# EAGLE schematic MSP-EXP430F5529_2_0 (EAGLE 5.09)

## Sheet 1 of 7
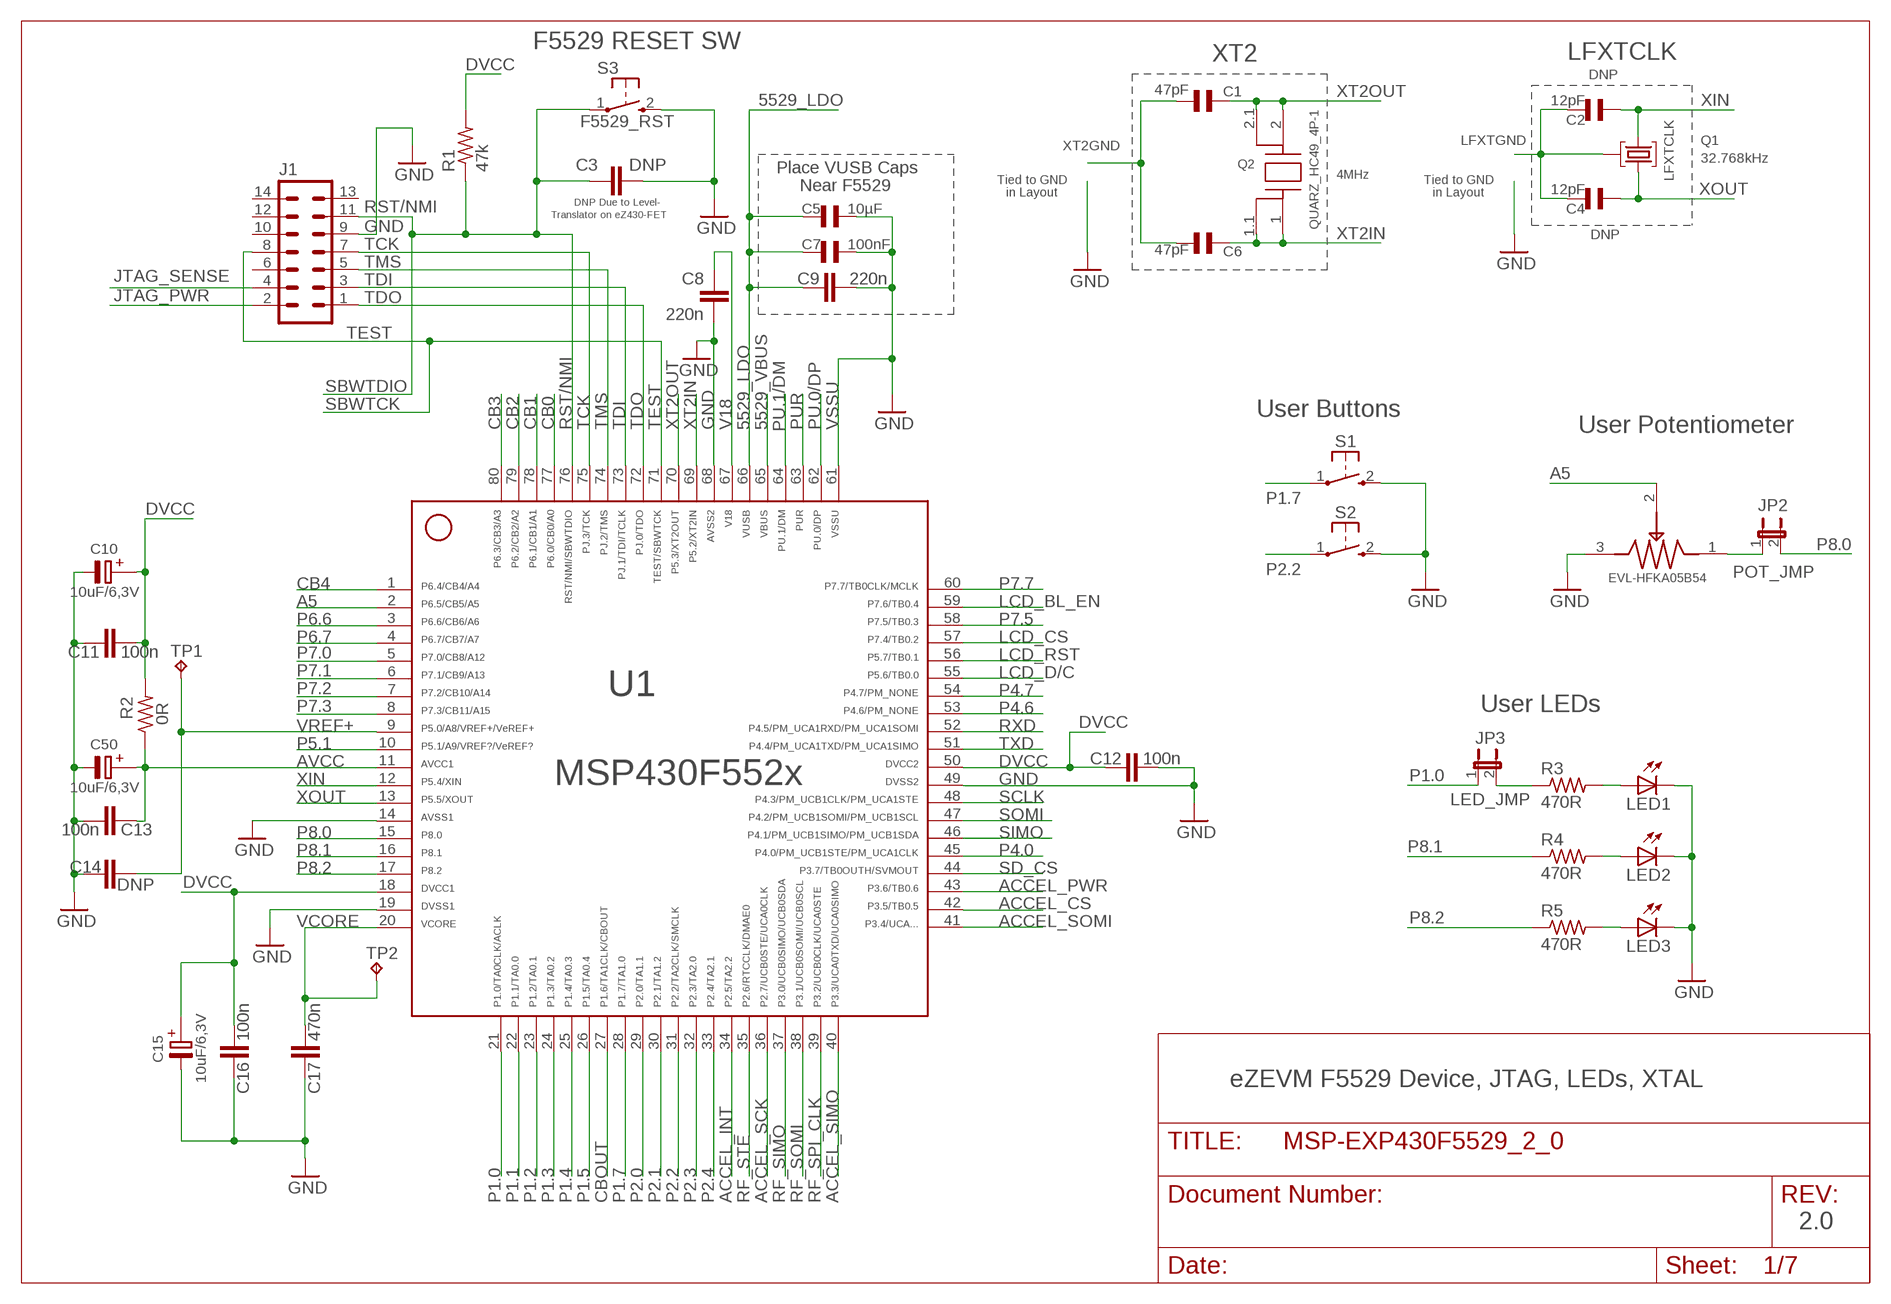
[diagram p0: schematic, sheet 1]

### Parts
C1  47pF  CSMD0805  [CSMD0805]
C2  12pF  CSMD0805  [CSMD0805]
C3  DNP  C-EUC0603  [C0603]
C4  12pF  CSMD0805  [CSMD0805]
C5  10µF  CSMD0805  [CSMD0805]
C6  47pF  CSMD0805  [CSMD0805]
C7  100nF  CSMD0805  [CSMD0805]
C8  220n  C-EUC0603  [C0603]
C9  220n  C-EUC0603  [C0603]
C10  10uF/6,3V  ELKO_1210  [1210ELKO]
C11  100n  C-EUC0603  [C0603]
C12  100n  C-EUC0805  [C0805]
C13  100n  C-EUC0805  [C0805]
C14  DNP  C-EUC0603  [C0603]
C15  10uF/6,3V  ELKO_1210  [1210ELKO]
C16  100n  C-EUC0805  [C0805]
C17  470n  C-EUC0805  [C0805]
C50  10uF/6,3V  ELKO_1210  [1210ELKO]
J1  ML14  [ML14]
JP2  POT_JMP  JP1E\SMALL_PIN  [JP1S]
JP3  LED_JMP  JP1E\SMALL_PIN  [JP1S]
LED1  LEDCHIPLED_0603  [CHIPLED_0603]
LED2  LEDCHIPLED_0603  [CHIPLED_0603]
LED3  LEDCHIPLED_0603  [CHIPLED_0603]
POT1  EVL-HFKA05B54  EVL-HFAA05B54  [EVL-HFAA05B54]
Q1  32.768kHz  F20XX_PIR_DEMO_&_EVAL_CM200T  [F20XX_PIR_DEMO_&_EVAL_CMJ206T]
Q2  QUARZ_HC49_4P-1  [QUARZ_HC49_4P]
R1  47k  R-US_R0603  [R0603]
R2  0R  R-US_R0603  [R0603]
R3  470R  R-US_R0603  [R0603]
R4  470R  R-US_R0603  [R0603]
R5  470R  R-US_R0603  [R0603]
S1  PB  [PBTH]
S2  PB  [PBTH]
S3  F5529_RST  PB  [PBTH]
TP1  TP  [TP]
TP2  TP  [TP]
U1  MSP430F5529IPNR  F552X---PN80  [PN80]

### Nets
5529_LDO [Power]: C5.1 C7.1 C9.1 U1.66 ; also sheet 3,4
5529_VBUS [Power]: U1.65 ; also sheet 3,4
A5: POT1.2(X2) U1.2
ACCEL_CS: U1.42 ; also sheet 2
ACCEL_INT: U1.34 ; also sheet 2
ACCEL_PWR: U1.43 ; also sheet 2
ACCEL_SCK: U1.36 ; also sheet 2
ACCEL_SIMO: U1.40 ; also sheet 2
ACCEL_SOMI: U1.41 ; also sheet 2
AVCC: C13.1 C50.+ R2.1 U1.11
CB0: U1.77 ; also sheet 2
CB1: U1.78 ; also sheet 2
CB2: U1.79 ; also sheet 2
CB3: U1.80 ; also sheet 2
CB4: U1.1 ; also sheet 2
CBOUT: U1.27 ; also sheet 2
DVCC [Power]: C10.+ C11.2 C12.1 C15.+ C16.2 R1.2 R2.2 U1.18 U1.50 ; also sheet 3,5
GND [Ground]: C3.1 C5.2 C7.2 C8.2 C9.2 C10.- C11.1 C12.2 C13.2 C14.1 C15.- C16.1 C17.1 C50.- J1.9 LED1.C LED2.C LED3.C POT1.3(X3) S1.2(S) S2.2(S) S3.2(S) U1.14 U1.19 U1.49 U1.61 U1.68 ; also sheet 2,3,4,5,6
JTAG_PWR [Power]: J1.2 ; also sheet 3
JTAG_SENSE: J1.4 ; also sheet 3
LCD_BL_EN: U1.59 ; also sheet 3
LCD_CS: U1.57 ; also sheet 3
LCD_D/C: U1.55 ; also sheet 3
LCD_RST: U1.56 ; also sheet 3
LFXTGND: C2.2 C4.2 Q1.P3(GND)
N$21: LED3.A R5.2
N$32: LED1.A R3.2
N$35: LED2.A R4.2
N$36: JP3.2 R3.1
N$43: JP2.1 POT1.1(X1)
P1.0: JP3.1 U1.21 ; also sheet 4
P1.1: U1.22 ; also sheet 2
P1.2: U1.23 ; also sheet 2
P1.3: U1.24 ; also sheet 2
P1.4: U1.25 ; also sheet 2
P1.5: U1.26 ; also sheet 2
P1.7: S1.1(P) U1.28
P2.0: U1.29 ; also sheet 4
P2.1: U1.30 ; also sheet 4
P2.2: S2.1(P) U1.31
P2.3: U1.32 ; also sheet 4
P2.4: U1.33 ; also sheet 4
P4.0: U1.45 ; also sheet 2,4
P4.6: U1.53 ; also sheet 2,4
P4.7: U1.54 ; also sheet 2,4
P5.1: U1.10 ; also sheet 2
P6.6: U1.3 ; also sheet 2,4
P6.7: U1.4 ; also sheet 2
P7.0: U1.5 ; also sheet 2
P7.1: U1.6 ; also sheet 2
P7.2: U1.7 ; also sheet 2
P7.3: U1.8 ; also sheet 2
P7.5: U1.58 ; also sheet 4
P7.7: U1.60 ; also sheet 2
P8.0: JP2.2 U1.15 ; also sheet 2
P8.1: R4.1 U1.16 ; also sheet 2
P8.2: R5.1 U1.17 ; also sheet 2
PU.0/DP: U1.62 ; also sheet 4
PU.1/DM: U1.64 ; also sheet 4
PUR: U1.63 ; also sheet 4
RF_SIMO: U1.37 ; also sheet 4
RF_SOMI: U1.38 ; also sheet 4
RF_SPI_CLK: U1.39 ; also sheet 4
RF_STE: U1.35 ; also sheet 4
RST/NMI: C3.2 J1.11 R1.1 S3.1(P) U1.76 ; also sheet 5
RXD: U1.52 ; also sheet 2,4,5
SCLK: U1.48 ; also sheet 2,3
SD_CS: U1.44 ; also sheet 2
SIMO: U1.46 ; also sheet 2,3
SOMI: U1.47 ; also sheet 2
TCK: J1.7 U1.75
TDI: J1.3 U1.73
TDO: J1.1 U1.72
TEST: J1.8 U1.71 ; also sheet 5
TMS: J1.5 U1.74
TXD: U1.51 ; also sheet 2,4,5
V18: C8.1 U1.67
VCORE: C17.2 TP2.1(TP) U1.20
VREF+: C14.2 TP1.1(TP) U1.9
XIN: C2.1 Q1.P2 U1.12
XOUT: C4.1 Q1.P1 U1.13
XT2GND [Ground]: C1.2 C6.2
XT2IN: C6.1 Q2.1 Q2.1.1 U1.69
XT2OUT: C1.1 Q2.2 Q2.2.1 U1.70
Unconnected: J1.6 J1.10 J1.12 J1.13 J1.14

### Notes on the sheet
- F5529 RESET SW
- XT2 | LFXTCLK
- DNP
- Place VUSB Caps | 4MHz
- Tied to GND | Tied to GND | LFXTCLK
- Near F5529
- in Layout | in Layout
- DNP Due to Level-
- Translator on eZ430-FET
- DNP
- SBWTDIO
- SBWTCK
- User Buttons
- VSSU | User Potentiometer
- EVL-HFKA05B54
- User LEDs
- eZEVM F5529 Device, JTAG, LEDs, XTAL
- 2.0

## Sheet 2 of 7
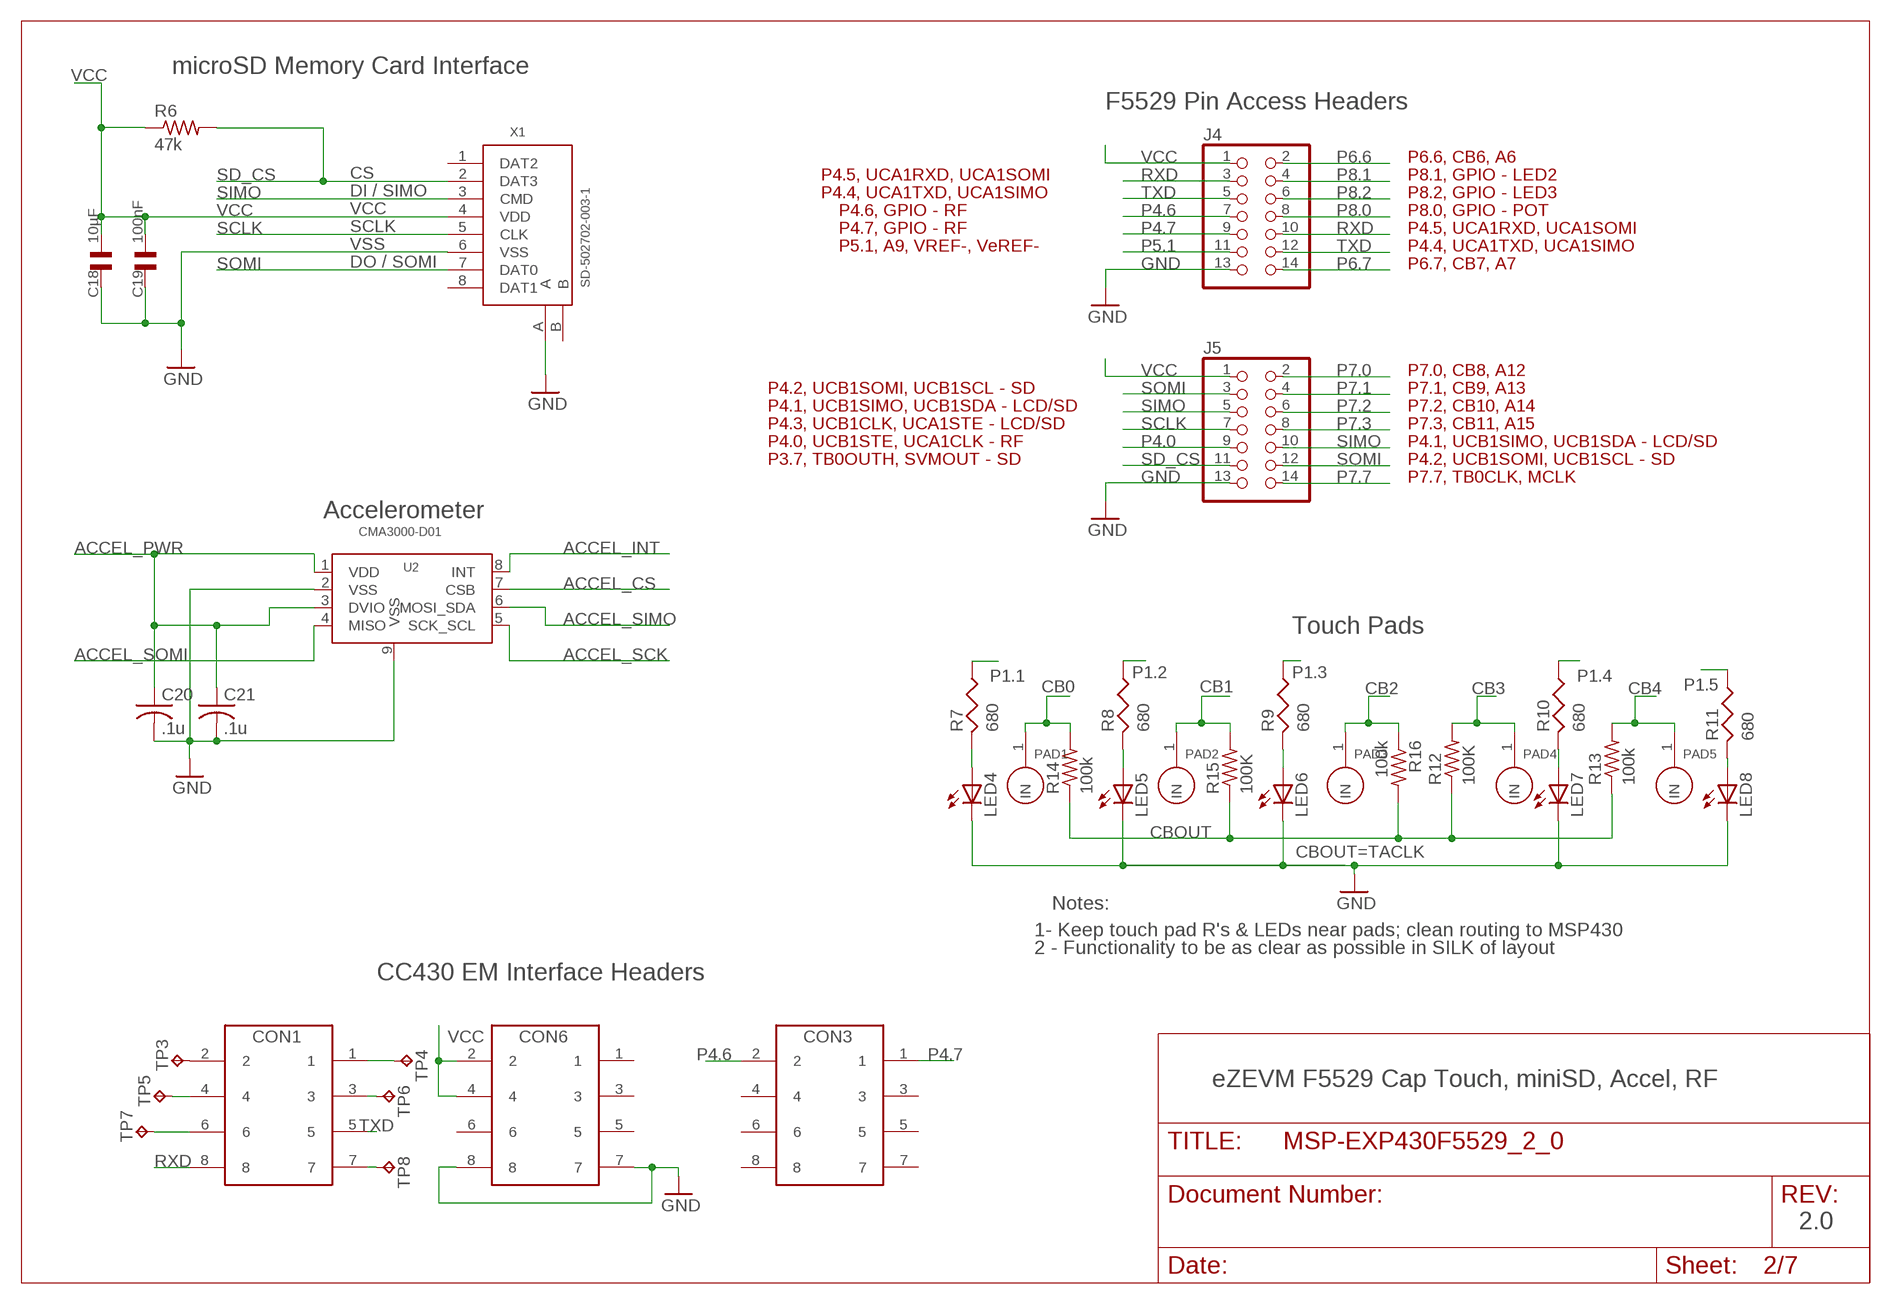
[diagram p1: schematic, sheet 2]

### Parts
C18  10µF  CSMD0805  [CSMD0805]
C19  100nF  CSMD0805  [CSMD0805]
C20  .1u  C-USC0603  [C0603]
C21  .1u  C-USC0603  [C0603]
CON1  8PIN_SM_MA_HEADER  [8PIN_SM_MA_HEADER]
CON2  8PIN_SM_MA_HEADER  [8PIN_SM_MA_HEADER]
CON3  8PIN_SM_MA_HEADER  [8PIN_SM_MA_HEADER]
J4  PINHD-2X7  [2X07]
J5  PINHD-2X7  [2X07]
LED4  LEDTOPLED-SANTANA  [MINI-TOPLED-SANTANA]
LED5  LEDTOPLED-SANTANA  [MINI-TOPLED-SANTANA]
LED6  LEDTOPLED-SANTANA  [MINI-TOPLED-SANTANA]
LED7  LEDTOPLED-SANTANA  [MINI-TOPLED-SANTANA]
LED8  LEDTOPLED-SANTANA  [MINI-TOPLED-SANTANA]
PAD1  PROJECT7264_CC430_PAD  [CC430_PAD_NS]
PAD2  PROJECT7264_CC430_PAD  [CC430_PAD_NS]
PAD3  PROJECT7264_CC430_PAD  [CC430_PAD_NS]
PAD4  PROJECT7264_CC430_PAD  [CC430_PAD_NS]
PAD5  PROJECT7264_CC430_PAD  [CC430_PAD_NS]
R6  47k  R-US_R0603  [R0603]
R7  680  RES0805  [R0805]
R8  680  RES0805  [R0805]
R9  680  RES0805  [R0805]
R10  680  RES0805  [R0805]
R11  680  RES0805  [R0805]
R12  100K  R-US_R0603  [R0603]
R13  100k  R-US_R0603  [R0603]
R14  100k  R-US_R0603  [R0603]
R15  100K  R-US_R0603  [R0603]
R16  100k  R-US_R0603  [R0603]
TP3  TP  [TP]
TP4  TP  [TP]
TP5  TP  [TP]
TP6  TP  [TP]
TP7  TP  [TP]
TP8  TP  [TP]
U2  CMA3000-D01  CMA3000-D01-1  [CMA3000-D01]
X1  SD-502702-003-1  [SD-502702-003]

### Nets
ACCEL_CS: U2.7(CSB) ; also sheet 1
ACCEL_INT: U2.8(INT) ; also sheet 1
ACCEL_PWR: C20.1 C21.1 U2.1(VDD) U2.3(DVIO) ; also sheet 1
ACCEL_SCK: U2.5(SCK_SCL) ; also sheet 1
ACCEL_SIMO: U2.6(MOSI_SDA) ; also sheet 1
ACCEL_SOMI: U2.4(MISO) ; also sheet 1
CB0: PAD1.1(IN) R14.2 ; also sheet 1
CB1: PAD2.1(IN) R15.2 ; also sheet 1
CB2: PAD3.1(IN) R16.1 ; also sheet 1
CB3: PAD4.1(IN) R12.2 ; also sheet 1
CB4: PAD5.1(IN) R13.2 ; also sheet 1
CBOUT: R12.1 R13.1 R14.1 R15.1 R16.2 ; also sheet 1
GND [Ground]: C18.1 C19.1 C20.2 C21.2 CON2.7 CON2.8 J4.13 J5.13 LED4.C LED5.C LED6.C LED7.C LED8.C U2.2(VSS) U2.9(VSS) X1.6(VSS) X1.A ; also sheet 1,3,4,5,6
N$7: LED7.A R10.2
N$8: LED5.A R8.2
N$10: LED6.A R9.2
N$11: LED4.A R7.2
N$12: CON1.6 TP7.1(TP)
N$13: LED8.A R11.2
N$20: CON1.4 TP5.1(TP)
N$27: CON1.2 TP3.1(TP)
N$28: CON1.1 TP4.1(TP)
N$29: CON1.3 TP6.1(TP)
N$38: CON1.7 TP8.1(TP)
P1.1: R7.1 ; also sheet 1
P1.2: R8.1 ; also sheet 1
P1.3: R9.1 ; also sheet 1
P1.4: R10.1 ; also sheet 1
P1.5: R11.1 ; also sheet 1
P4.0: J5.9 ; also sheet 1,4
P4.6: CON3.2 J4.7 ; also sheet 1,4
P4.7: CON3.1 J4.9 ; also sheet 1,4
P5.1: J4.11 ; also sheet 1
P6.6: J4.2 ; also sheet 1,4
P6.7: J4.14 ; also sheet 1
P7.0: J5.2 ; also sheet 1
P7.1: J5.4 ; also sheet 1
P7.2: J5.6 ; also sheet 1
P7.3: J5.8 ; also sheet 1
P7.7: J5.14 ; also sheet 1
P8.0: J4.8 ; also sheet 1
P8.1: J4.4 ; also sheet 1
P8.2: J4.6 ; also sheet 1
RXD: CON1.8 J4.3 J4.10 ; also sheet 1,4,5
SCLK: J5.7 X1.5(CLK) ; also sheet 1,3
SD_CS: J5.11 R6.2 X1.2(DAT3) ; also sheet 1
SIMO: J5.5 J5.10 X1.3(CMD) ; also sheet 1,3
SOMI: J5.3 J5.12 X1.7(DAT0) ; also sheet 1
TXD: CON1.5 J4.5 J4.12 ; also sheet 1,4,5
VCC [Power]: C18.2 C19.2 CON2.2 CON2.4 J4.1 J5.1 R6.1 X1.4(VDD) ; also sheet 3,4
Unconnected: CON2.1 CON2.3 CON2.5 CON2.6 CON3.3 CON3.4 CON3.5 CON3.6 CON3.7 CON3.8 X1.1(DAT2) X1.8(DAT1) X1.B

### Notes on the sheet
- microSD Memory Card Interface
- F5529 Pin Access Headers
- P6.6, CB6, A6
- CS | P4.5, UCA1RXD, UCA1SOMI | P8.1, GPIO - LED2
- DI / SIMO | P4.4, UCA1TXD, UCA1SIMO | P8.2, GPIO - LED3
- VCC | P4.6, GPIO - RF | P8.0, GPIO - POT
- SCLK | P4.7, GPIO - RF | P4.5, UCA1RXD, UCA1SOMI
- VSS | P5.1, A9, VREF-, VeREF- | P4.4, UCA1TXD, UCA1SIMO
- DO / SOMI | P6.7, CB7, A7
- P7.0, CB8, A12
- P4.2, UCB1SOMI, UCB1SCL - SD | P7.1, CB9, A13
- P4.1, UCB1SIMO, UCB1SDA - LCD/SD | P7.2, CB10, A14
- P4.3, UCB1CLK, UCA1STE - LCD/SD | P7.3, CB11, A15
- P4.0, UCB1STE, UCA1CLK - RF | P4.1, UCB1SIMO, UCB1SDA - LCD/SD
- P3.7, TB0OUTH, SVMOUT - SD | P4.2, UCB1SOMI, UCB1SCL - SD
- P7.7, TB0CLK, MCLK
- Accelerometer
- Touch Pads
- CBOUT=TACLK
- Notes:
- 1- Keep touch pad R's & LEDs near pads; clean routing to MSP430
- 2 - Functionality to be as clear as possible in SILK of layout
- CC430 EM Interface Headers
- CON1 | CON6 | CON3
- eZEVM F5529 Cap Touch, miniSD, Accel, RF
- 2.0

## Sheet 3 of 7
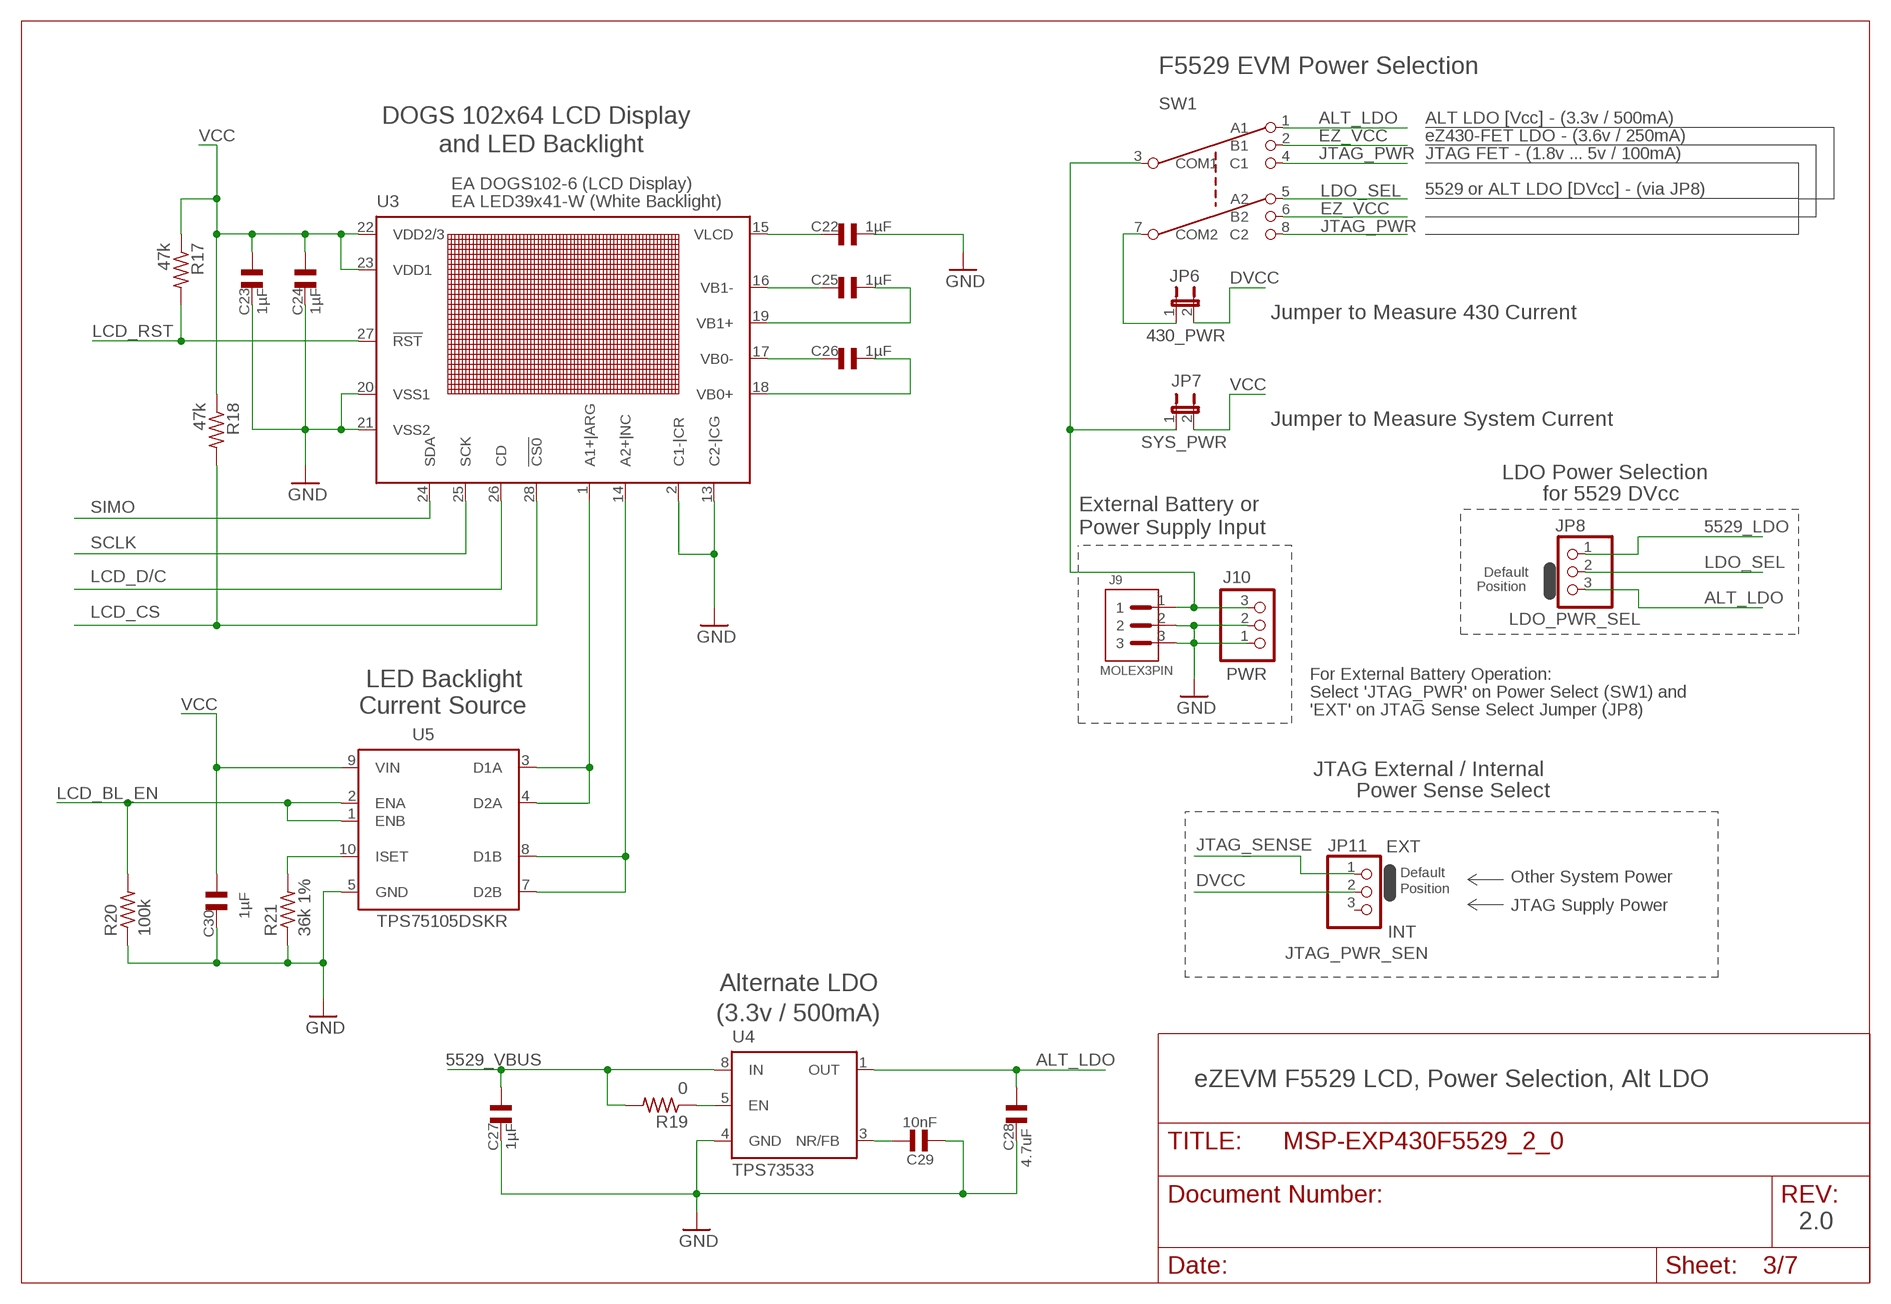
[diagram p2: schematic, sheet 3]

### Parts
C22  1µF  CSMD0805  [CSMD0805]
C23  1µF  CSMD0805  [CSMD0805]
C24  1µF  CSMD0805  [CSMD0805]
C25  1µF  CSMD0805  [CSMD0805]
C26  1µF  CSMD0805  [CSMD0805]
C27  1µF  CSMD0805  [CSMD0805]
C28  4.7uF  CSMD0805  [CSMD0805]
C29  10nF  CSMD0805  [CSMD0805]
C30  1µF  CSMD0805  [CSMD0805]
J9  MOLEX3PIN  [MOLEX-3P-HEADER]
J10  PWR  PINHD-1X3  [1X03]
JP6  430_PWR  JP1E  [JP1]
JP7  SYS_PWR  JP1E  [JP1]
JP8  LDO_PWR_SEL  PINHD-1X3/SMALL_PIN  [1X03S]
JP11  JTAG_PWR_SEN  PINHD-1X3/SMALL_PIN  [1X03S]
R17  47k  R-US_R0603  [R0603]
R18  47k  R-US_R0603  [R0603]
R19  0  R-US_R0603  [R0603]
R20  100k  R-US_R0603  [R0603]
R21  36k 1%  R-US_R0603  [R0603]
SW1  3PDT  [3PDT]
U3  EA DOGS102-6 (LCD Display)  EADOGS102-6  [EADOGS102-6]
U4  TPS73533  TPS735  [DRB_S-PVSON-N8]
U5  TPS75105DSKR  TPS7510X  [DSK_S-PDSO-N10]

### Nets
5529_LDO [Power]: JP8.1 ; also sheet 1,4
5529_VBUS [Power]: C27.2 R19.2 U4.8(IN) ; also sheet 1,4
ALT_LDO [Power]: C28.2 JP8.3 SW1.1(A1) U4.1(OUT)
D1A: U3.1(A1+|ARG) U5.3(D1A) U5.4(D2A)
D1B: U3.14(A2+|NC) U5.7(D2B) U5.8(D1B)
DVCC [Power]: JP6.2 JP11.2 ; also sheet 1,5
DVCC_SW [Power]: JP6.1 SW1.7(COM2)
EZ_VCC [Power]: SW1.2(B1) SW1.6(B2) ; also sheet 5,6
GND [Ground]: C22.2 C23.1 C24.1 C27.1 C28.1 C29.1 C30.1 J9.2 J9.3 J10.1 J10.2 R20.1 R21.1 U3.2(C1-|CR) U3.13(C2-|CG) U3.20(VSS1) U3.21(VSS2) U4.4(GND) U5.5(GND) ; also sheet 1,2,4,5,6
ISET: R21.2 U5.10(ISET)
JTAG_PWR [Power]: SW1.4(C1) SW1.8(C2) ; also sheet 1
JTAG_SENSE: JP11.1 ; also sheet 1
LCD_BL_EN: R20.2 U5.1(ENB) U5.2(ENA) ; also sheet 1
LCD_CS: R18.2 U3.28(!CS0) ; also sheet 1
LCD_D/C: U3.26(CD) ; also sheet 1
LCD_RST: R17.2 U3.27(!RST) ; also sheet 1
LDO_SEL [Power]: JP8.2 SW1.5(A2)
N$14: R19.1 U4.5(EN)
N$41: C25.1 U3.16(VB1-)
N$44: C25.2 U3.19(VB1+)
N$45: C26.1 U3.17(VB0-)
N$46: C26.2 U3.18(VB0+)
N$50: C29.2 U4.3(NR/FB)
SCLK: U3.25(SCK) ; also sheet 1,2
SIMO: U3.24(SDA) ; also sheet 1,2
VCC [Power]: C23.2 C24.2 C30.2 JP7.2 R17.1 R18.1 U3.22(VDD2/3) U3.23(VDD1) U5.9(VIN) ; also sheet 2,4
VCC_SW [Power]: J9.1 J10.3 JP7.1 SW1.3(COM1)
VLCD: C22.1 U3.15(VLCD)
Unconnected: JP11.3

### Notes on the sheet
- F5529 EVM Power Selection
- DOGS 102x64 LCD Display | ALT LDO [Vcc] - (3.3v / 500mA)
- eZ430-FET LDO - (3.6v / 250mA)
- and LED Backlight
- JTAG FET - (1.8v ... 5v / 100mA)
- 5529 or ALT LDO [DVcc] - (via JP8)
- EA LED39x41-W (White Backlight)
- Jumper to Measure 430 Current
- Jumper to Measure System Current
- LDO Power Selection
- for 5529 DVcc
- External Battery or
- Power Supply Input
- Default
- Position
- For External Battery Operation:
- LED Backlight
- Select 'JTAG_PWR' on Power Select (SW1) and
- Current Source | 'EXT' on JTAG Sense Select Jumper (JP8)
- JTAG External / Internal
- Power Sense Select
- EXT
- Default
- Other System Power
- Position
- JTAG Supply Power
- INT
- Alternate LDO
- (3.3v / 500mA)
- eZEVM F5529 LCD, Power Selection, Alt LDO
- 2.0

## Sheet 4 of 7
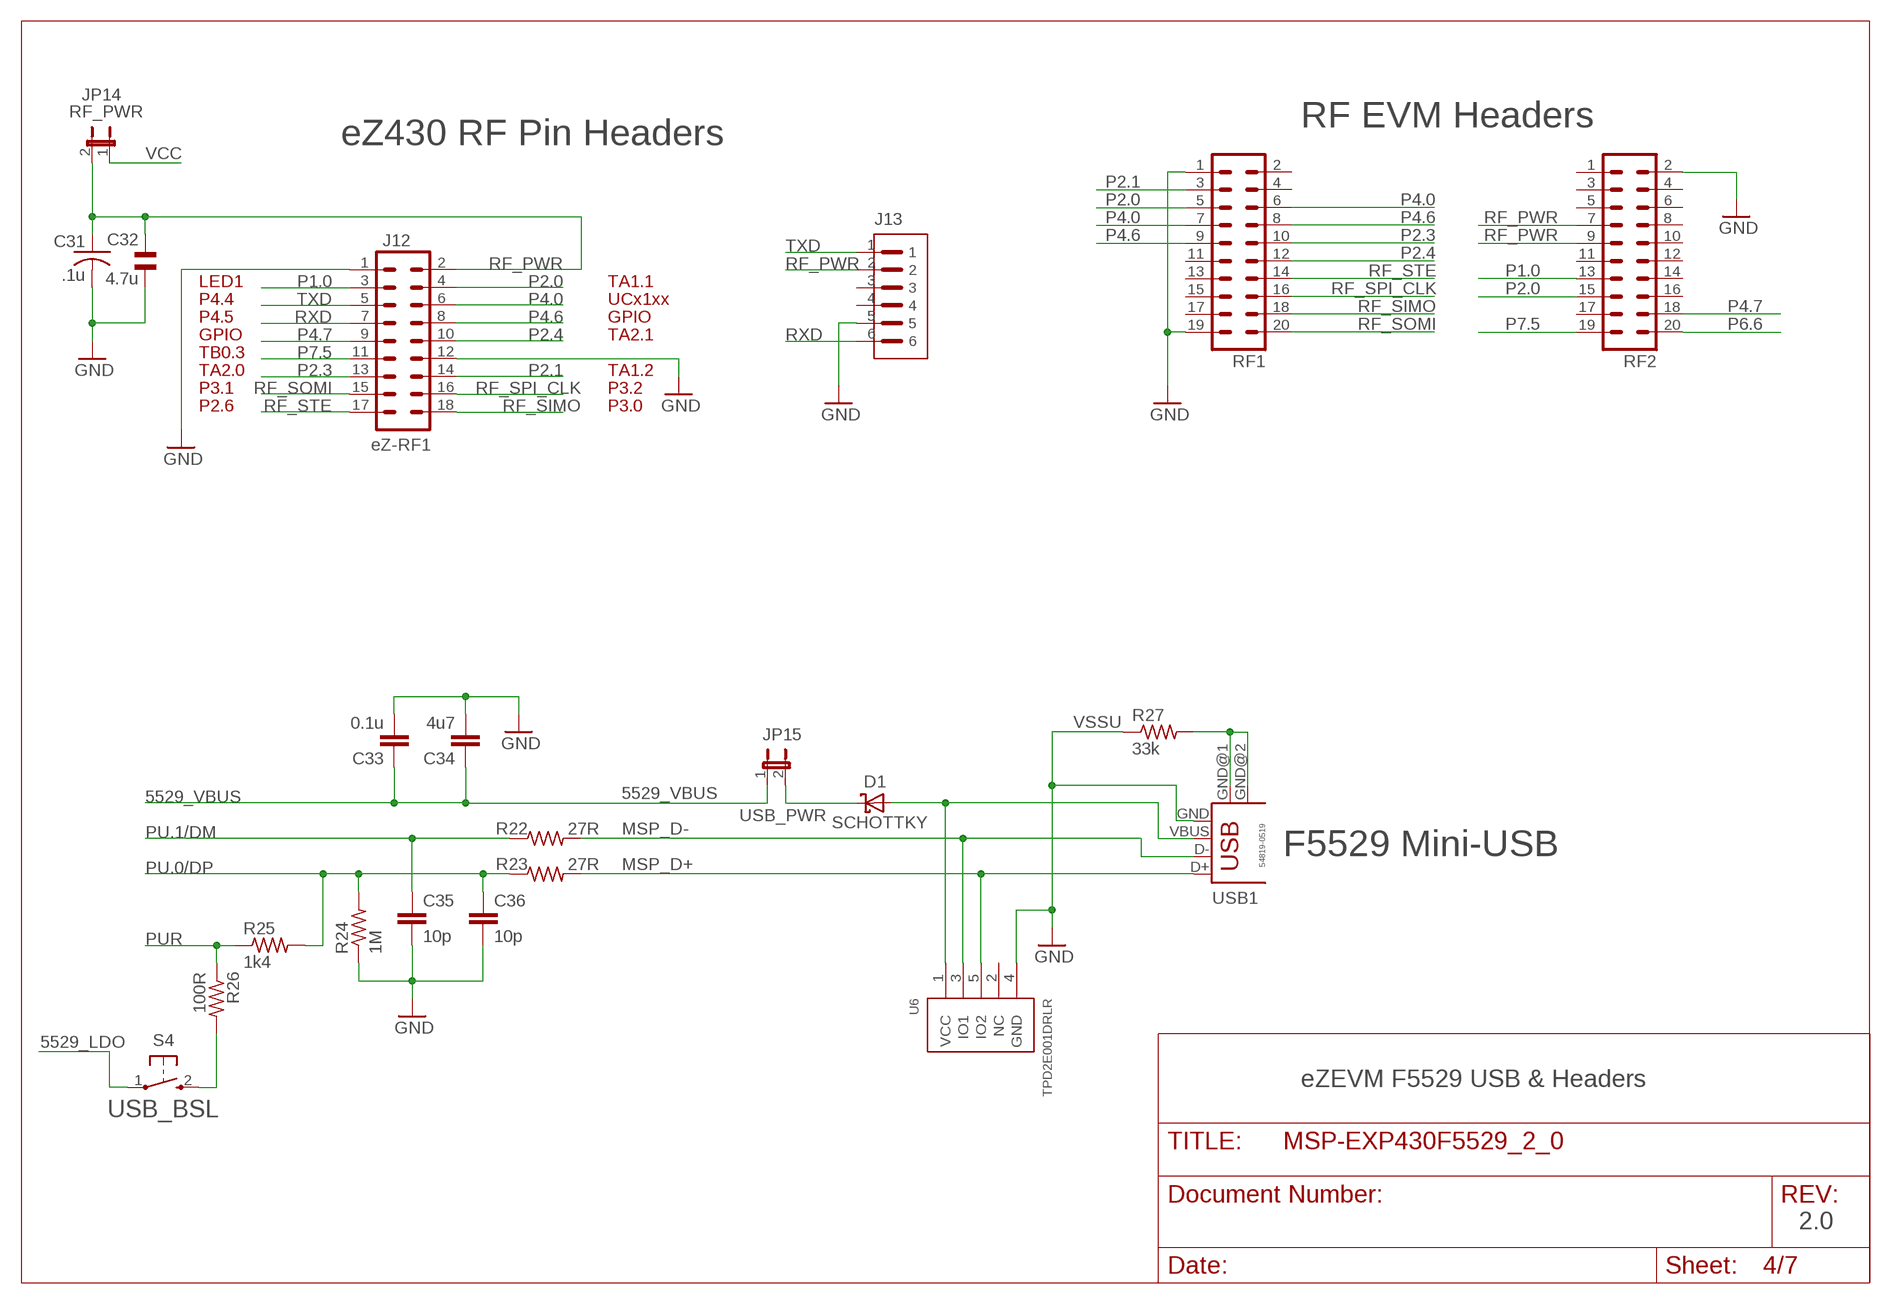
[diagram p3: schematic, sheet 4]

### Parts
C31  .1u  C-USC0603  [C0603]
C32  4.7u  CSMD0805  [CSMD0805]
C33  0.1u  C-EUC0603  [C0603]
C34  4u7  C-EUC0603  [C0603]
C35  10p  C-EUC0603  [C0603]
C36  10p  C-EUC0603  [C0603]
D1  SCHOTTKY  SCHOTTKY-MINI-MELF  [MINIMELF]
J12  eZ-RF1  _MSP430_RF_MA09-2  [_MSP430_RF_MA09-2]
J13  eZRF  SL127P6  [SL127L6]
JP14  RF_PWR  JP1E  [JP1]
JP15  USB_PWR  JP1E  [JP1]
R22  27R  R-US_R0603  [R0603]
R23  27R  R-US_R0603  [R0603]
R24  1M  R-US_R0603  [R0603]
R25  1k4  R-US_R0603  [R0603]
R26  100R  R-US_R0603  [R0603]
R27  33k  R-US_R0603  [R0603]
RF1  TFM-110-02-SM-D-A-K  [TFM-110-02-SM-D-A-K]
RF2  TFM-110-02-SM-D-A-K  [TFM-110-02-SM-D-A-K]
S4  USB_BSL  PB  [PBTH]
U6  TPD2E001DRLR  TPD2E001  [TPD2E001-DRL]
USB1  F5529 Mini-USB  USB-MB-H  [USB-MB-H]

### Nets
5529_LDO [Power]: S4.1(P) ; also sheet 1,3
5529_VBUS [Power]: C33.1 C34.1 JP15.1 ; also sheet 1,3
GND [Ground]: C31.2 C32.2 C33.2 C34.2 C35.2 C36.2 J12.1 J12.12 J13.5 R24.1 R27.1 RF1.1 RF1.19 RF2.2 U6.4(GND) USB1.GND ; also sheet 1,2,3,5,6
MSP_D+: R23.2 U6.5(IO2) USB1.D+
MSP_D-: R22.2 U6.3(IO1) USB1.D-
N$24: D1.C JP15.2
N$39: R27.2 USB1.GND@1(GND) USB1.GND@2(GND)
N$40: R26.2 S4.2(S)
N$42: D1.A U6.1(VCC) USB1.VBUS
P1.0: J12.3 RF2.13 ; also sheet 1
P2.0: J12.4 RF1.5 RF2.15 ; also sheet 1
P2.1: J12.14 RF1.3 ; also sheet 1
P2.3: J12.13 RF1.10 ; also sheet 1
P2.4: J12.10 RF1.12 ; also sheet 1
P4.0: J12.6 RF1.6 RF1.7 ; also sheet 1,2
P4.6: J12.8 RF1.8 RF1.9 ; also sheet 1,2
P4.7: J12.9 RF2.18 ; also sheet 1,2
P6.6: RF2.20 ; also sheet 1,2
P7.5: J12.11 RF2.19 ; also sheet 1
PU.0/DP: C36.1 R23.1 R24.2 R25.2 ; also sheet 1
PU.1/DM: C35.1 R22.1 ; also sheet 1
PUR: R25.1 R26.1 ; also sheet 1
RF_PWR: C31.1 C32.1 J12.2 J13.2 JP14.2 RF2.7 RF2.9
RF_SIMO: J12.18 RF1.18 ; also sheet 1
RF_SOMI: J12.15 RF1.20 ; also sheet 1
RF_SPI_CLK: J12.16 RF1.16 ; also sheet 1
RF_STE: J12.17 RF1.14 ; also sheet 1
RXD: J12.7 J13.6 ; also sheet 1,2,5
TXD: J12.5 J13.1 ; also sheet 1,2,5
VCC [Power]: JP14.1 ; also sheet 2,3
Unconnected: J13.3 J13.4 RF1.2 RF1.4 RF1.11 RF1.13 RF1.15 RF1.17 RF2.1 RF2.3 RF2.4 RF2.5 RF2.6 RF2.8 RF2.10 RF2.11 RF2.12 RF2.14 RF2.16 RF2.17 U6.2(NC)

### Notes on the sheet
- RF EVM Headers
- eZ430 RF Pin Headers
- LED1 | TA1.1
- P4.4 | UCx1xx
- P4.5 | GPIO
- GPIO | TA2.1
- TB0.3
- TA2.0 | TA1.2
- P3.1 | P3.2
- P2.6 | P3.0
- VSSU
- 54819-0519
- eZEVM F5529 USB & Headers
- 2.0

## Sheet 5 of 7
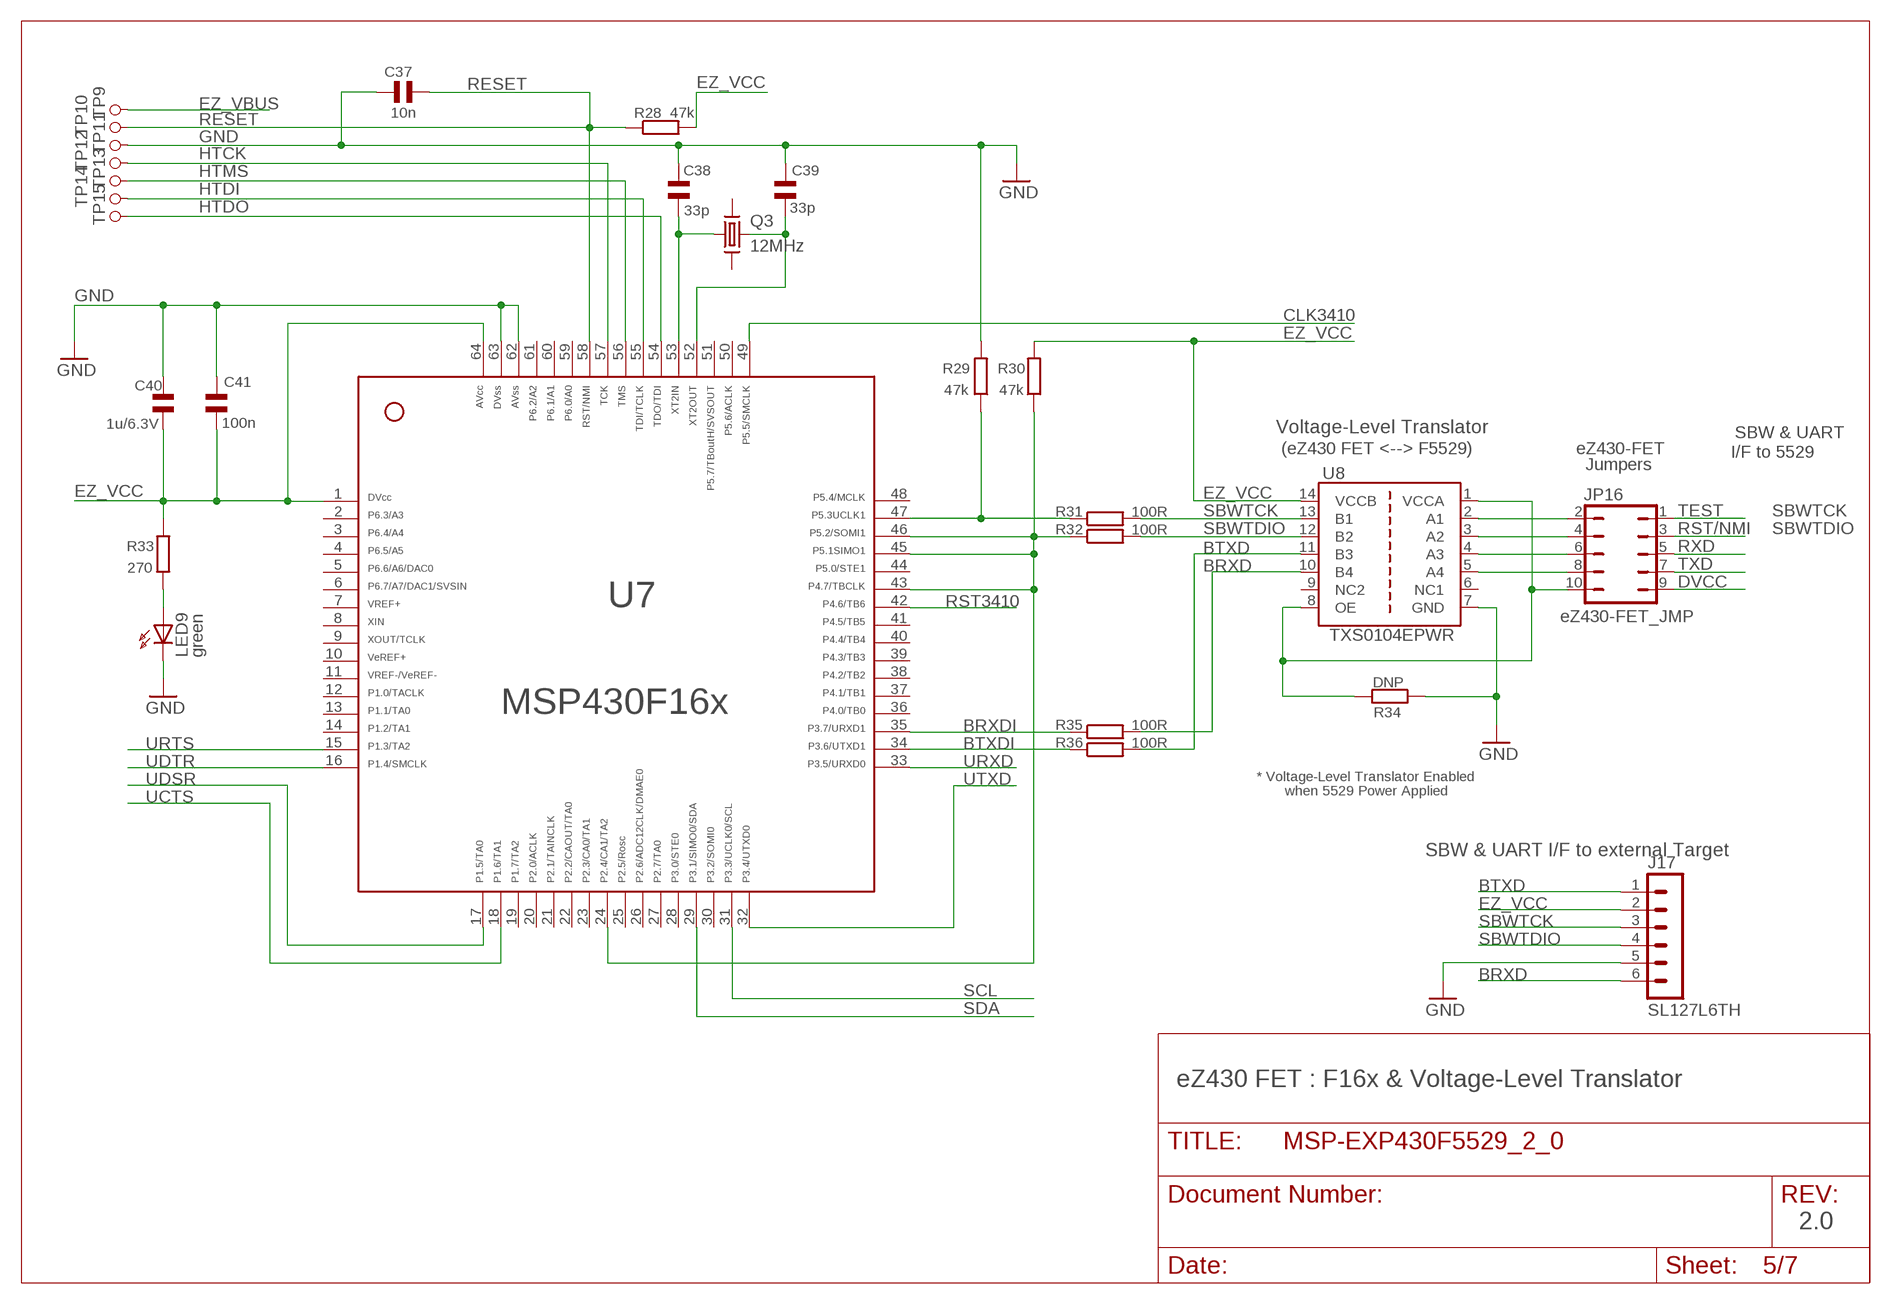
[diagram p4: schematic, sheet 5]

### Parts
C37  10n  C_SMD0402  [0402]
C38  33p  C_SMD0402  [0402]
C39  33p  C_SMD0402  [0402]
C40  1u/6.3V  C_SMD0603  [0603]
C41  100n  C_SMD0402  [0402]
J17  SL127L6TH  [SL127L6_MPE]
JP16  eZ430-FET_JMP  JP5Q  [JP5Q]
LED9  green  LED_0603D0603  [DIODE0603]
Q3  12MHz  XTL_FT7AFT10A  [FT10A]
R28  47k  R_SMDR0402  [0402]
R29  47k  R_SMDR0402  [0402]
R30  47k  R_SMDR0402  [0402]
R31  100R  R_SMDR0402  [0402]
R32  100R  R_SMDR0402  [0402]
R33  270  R_SMDR0402  [0402]
R34  DNP  R_SMDR0402  [0402]
R35  100R  R_SMDR0402  [0402]
R36  100R  R_SMDR0402  [0402]
TP9  TP05TP10  [TP10]
TP10  TP05TP10  [TP10]
TP11  TP05TP10  [TP10]
TP12  TP05TP10  [TP10]
TP13  TP05TP10  [TP10]
TP14  TP05TP10  [TP10]
TP15  TP05TP10  [TP10]
U7  MSP430F1612IPMR  F16X---PM64  [PM/PAG64]
U8  TXS0104EPWR  TXS0104E  [PW_R-PDSO-G14]

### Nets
BRXD: J17.6 R35.2 U8.10(B4)
BRXDI: R35.1 U7.35 ; also sheet 6
BTXD: J17.1 R36.2 U8.11(B3)
BTXDI: R36.1 U7.34 ; also sheet 6
CLK3410: U7.49 ; also sheet 6
DVCC [Power]: JP16.9 ; also sheet 1,3
EZ_VBUS [Power]: TP9.1 ; also sheet 6
EZ_VCC [Power]: C40.2 C41.1 J17.2 R28.2 R30.2 R33.2 U7.1 U7.64 U8.14(VCCB) ; also sheet 3,6
GND [Ground]: C37.2 C38.2 C39.2 C40.1 C41.2 J17.5 LED9.K(C) R29.2 R34.1 TP11.1 U7.62 U7.63 U8.7(GND) ; also sheet 1,2,3,4,6
HTCK: TP12.1 U7.57
HTDI: TP14.1 U7.55
HTDO: TP15.1 U7.54
HTMS: TP13.1 U7.56
N$1: R29.1 R31.1 U7.47
N$2: R30.1 R32.1 U7.24 U7.43 U7.45 U7.46
N$15: JP16.2 U8.2(A1)
N$19: LED9.A R33.1
N$23: JP16.4 U8.3(A2)
N$25: JP16.6 U8.4(A3)
N$33: JP16.8 U8.5(A4)
N$34: JP16.10 R34.2 U8.1(VCCA) U8.8(OE)
RESET: C37.1 R28.1 TP10.1 U7.58 ; also sheet 6
RST3410: U7.42 ; also sheet 6
RST/NMI: JP16.3 ; also sheet 1
RXD: JP16.5 ; also sheet 1,2,4
SBWTCK: J17.3 R31.2 U8.13(B1)
SBWTDIO: J17.4 R32.2 U8.12(B2)
SCL: U7.31 ; also sheet 6
SDA: U7.29 ; also sheet 6
TEST: JP16.1 ; also sheet 1
TXD: JP16.7 ; also sheet 1,2,4
UCTS: U7.18 ; also sheet 6
UDSR: U7.17 ; also sheet 6
UDTR: U7.16 ; also sheet 6
URTS: U7.15 ; also sheet 6
URXD: U7.33 ; also sheet 6
UTXD: U7.32 ; also sheet 6
XIN1: C39.1 Q3.P$3 U7.52
XOUT1: C38.1 Q3.P$1 U7.53
Unconnected: Q3.P$2(G2) Q3.P$4(G4) U7.2 U7.3 U7.4 U7.5 U7.6 U7.7 U7.8 U7.9 U7.10 U7.11 U7.12 U7.13 U7.14 U7.19 U7.20 U7.21 U7.22 U7.23 U7.25 U7.26 U7.27 U7.28 U7.30 U7.36 U7.37 U7.38 U7.39 U7.40 U7.41 U7.44 U7.48 U7.50 U7.51 U7.59 U7.60 U7.61 U8.6(NC1) U8.9(NC2)

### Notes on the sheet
- Voltage-Level Translator
- SBW & UART
- (eZ430 FET <--> F5529) | eZ430-FET | I/F to 5529
- Jumpers
- SBWTCK
- SBWTDIO
- * Voltage-Level Translator Enabled
- when 5529 Power Applied
- SBW & UART I/F to external Target
- eZ430 FET : F16x & Voltage-Level Translator
- 2.0

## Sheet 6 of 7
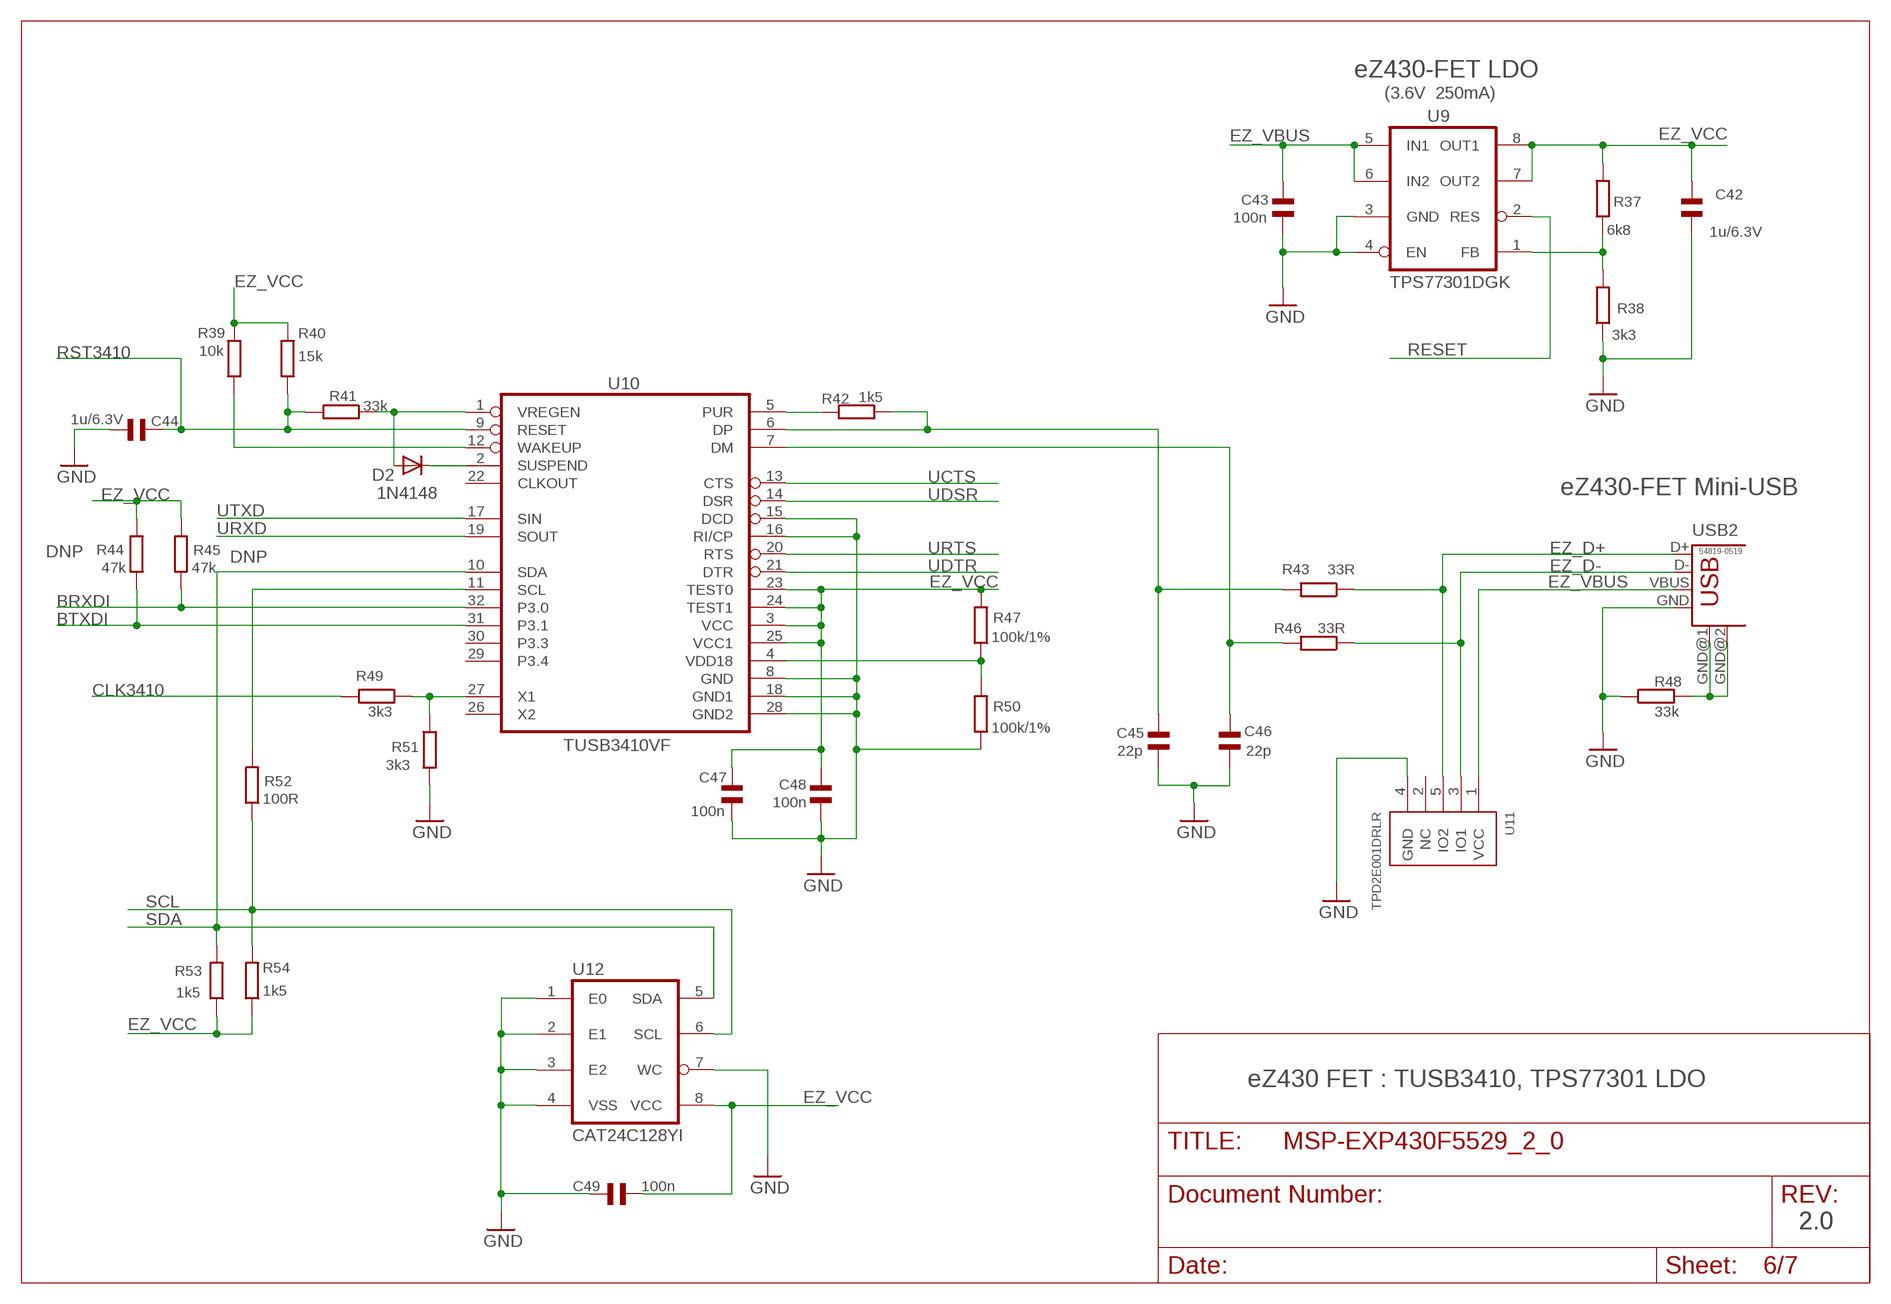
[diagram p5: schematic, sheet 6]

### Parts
C42  1u/6.3V  C_SMD0603  [0603]
C43  100n  C_SMD0402  [0402]
C44  1u/6.3V  C_SMD0603  [0603]
C45  22p  C_SMD0402  [0402]
C46  22p  C_SMD0402  [0402]
C47  100n  C_SMD0402  [0402]
C48  100n  C_SMD0402  [0402]
C49  100n  C_SMD0402  [0402]
D2  1N4148  DIODE-SOD110-R  [SOD110-R]
R37  6k8  R_SMDR0402  [0402]
R38  3k3  R_SMDR0402  [0402]
R39  10k  R_SMDR0402  [0402]
R40  15k  R_SMDR0402  [0402]
R41  33k  R_SMDR0402  [0402]
R42  1k5  R_SMDR0402  [0402]
R43  33R  R_SMDR0402  [0402]
R44  47k  R_SMDR0402  [0402]
R45  47k  R_SMDR0402  [0402]
R46  33R  R_SMDR0402  [0402]
R47  100k/1%  R_SMDR0402  [0402]
R48  33k  R_SMDR0402  [0402]
R49  3k3  R_SMDR0402  [0402]
R50  100k/1%  R_SMDR0402  [0402]
R51  3k3  R_SMDR0402  [0402]
R52  100R  R_SMDR0402  [0402]
R53  1k5  R_SMDR0402  [0402]
R54  1k5  R_SMDR0402  [0402]
U9  TPS77301DGK  TPS773XX  [MSOP8]
U10  TUSB3410VF  TUSB3410  [QFP32]
U11  TPD2E001DRLR  TPD2E001  [TPD2E001-DRL]
U12  CAT24C128YI  USBFET_M24XXX  [USBFET_TSSOP8]
USB2  eZ430-FET Mini-USB  USB-MB-H  [USB-MB-H]

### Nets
BRXDI: R45.1 U10.32(P3.0) ; also sheet 5
BTXDI: R44.1 U10.31(P3.1) ; also sheet 5
CLK3410: R49.2 ; also sheet 5
EZ_D+: R43.1 U11.5(IO2) USB2.D+
EZ_D-: R46.1 U11.3(IO1) USB2.D-
EZ_VBUS [Power]: C43.2 U9.5(IN1) U9.6(IN2) U11.1(VCC) USB2.VBUS ; also sheet 5
EZ_VCC [Power]: C42.1 C47.2 C48.2 C49.1 R37.2 R39.2 R40.2 R44.2 R45.2 R47.2 R53.1 R54.1 U9.7(OUT2) U9.8(OUT1) U10.3(VCC) U10.23(TEST0) U10.24(TEST1) U10.25(VCC1) U12.8(VCC) ; also sheet 3,5
GND [Ground]: C42.2 C43.1 C44.2 C45.1 C46.1 C47.1 C48.1 C49.2 R38.1 R48.1 R50.1 R51.2 U9.3(GND) U9.4(EN) U10.8(GND) U10.15(DCD) U10.16(RI/CP) U10.18(GND1) U10.28(GND2) U11.4(GND) U12.1(E0) U12.2(E1) U12.3(E2) U12.4(VSS) U12.7(WC) USB2.GND ; also sheet 1,2,3,4,5
N$3: R49.1 R51.1 U10.27(X1)
N$4: R37.1 R38.2 U9.1(FB)
N$5: D2.A R41.1 U10.1(VREGEN)
N$6: D2.C U10.2(SUSPEND)
N$9: R39.1 U10.12(WAKEUP)
N$16: R52.2 U10.11(SCL)
N$17: R47.1 R50.2 U10.4(VDD18)
N$22: R48.2 USB2.GND@1(GND) USB2.GND@2(GND)
N$26: R42.2 U10.5(PUR)
N$30: C46.2 R46.2 U10.7(DM)
N$31: C45.2 R42.1 R43.2 U10.6(DP)
RESET: U9.2(RES) ; also sheet 5
RST3410: C44.1 R40.1 R41.2 U10.9(RESET) ; also sheet 5
SCL: R52.1 R54.2 U12.6(SCL) ; also sheet 5
SDA: R53.2 U10.10(SDA) U12.5(SDA) ; also sheet 5
UCTS: U10.13(CTS) ; also sheet 5
UDSR: U10.14(DSR) ; also sheet 5
UDTR: U10.21(DTR) ; also sheet 5
URTS: U10.20(RTS) ; also sheet 5
URXD: U10.19(SOUT) ; also sheet 5
UTXD: U10.17(SIN) ; also sheet 5
Unconnected: U10.22(CLKOUT) U10.26(X2) U10.29(P3.4) U10.30(P3.3) U11.2(NC)

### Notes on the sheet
- eZ430-FET LDO
- (3.6V  250mA)
- DNP
- 54819-0519
- DNP
- eZ430 FET : TUSB3410, TPS77301 LDO
- 2.0 | 2.0

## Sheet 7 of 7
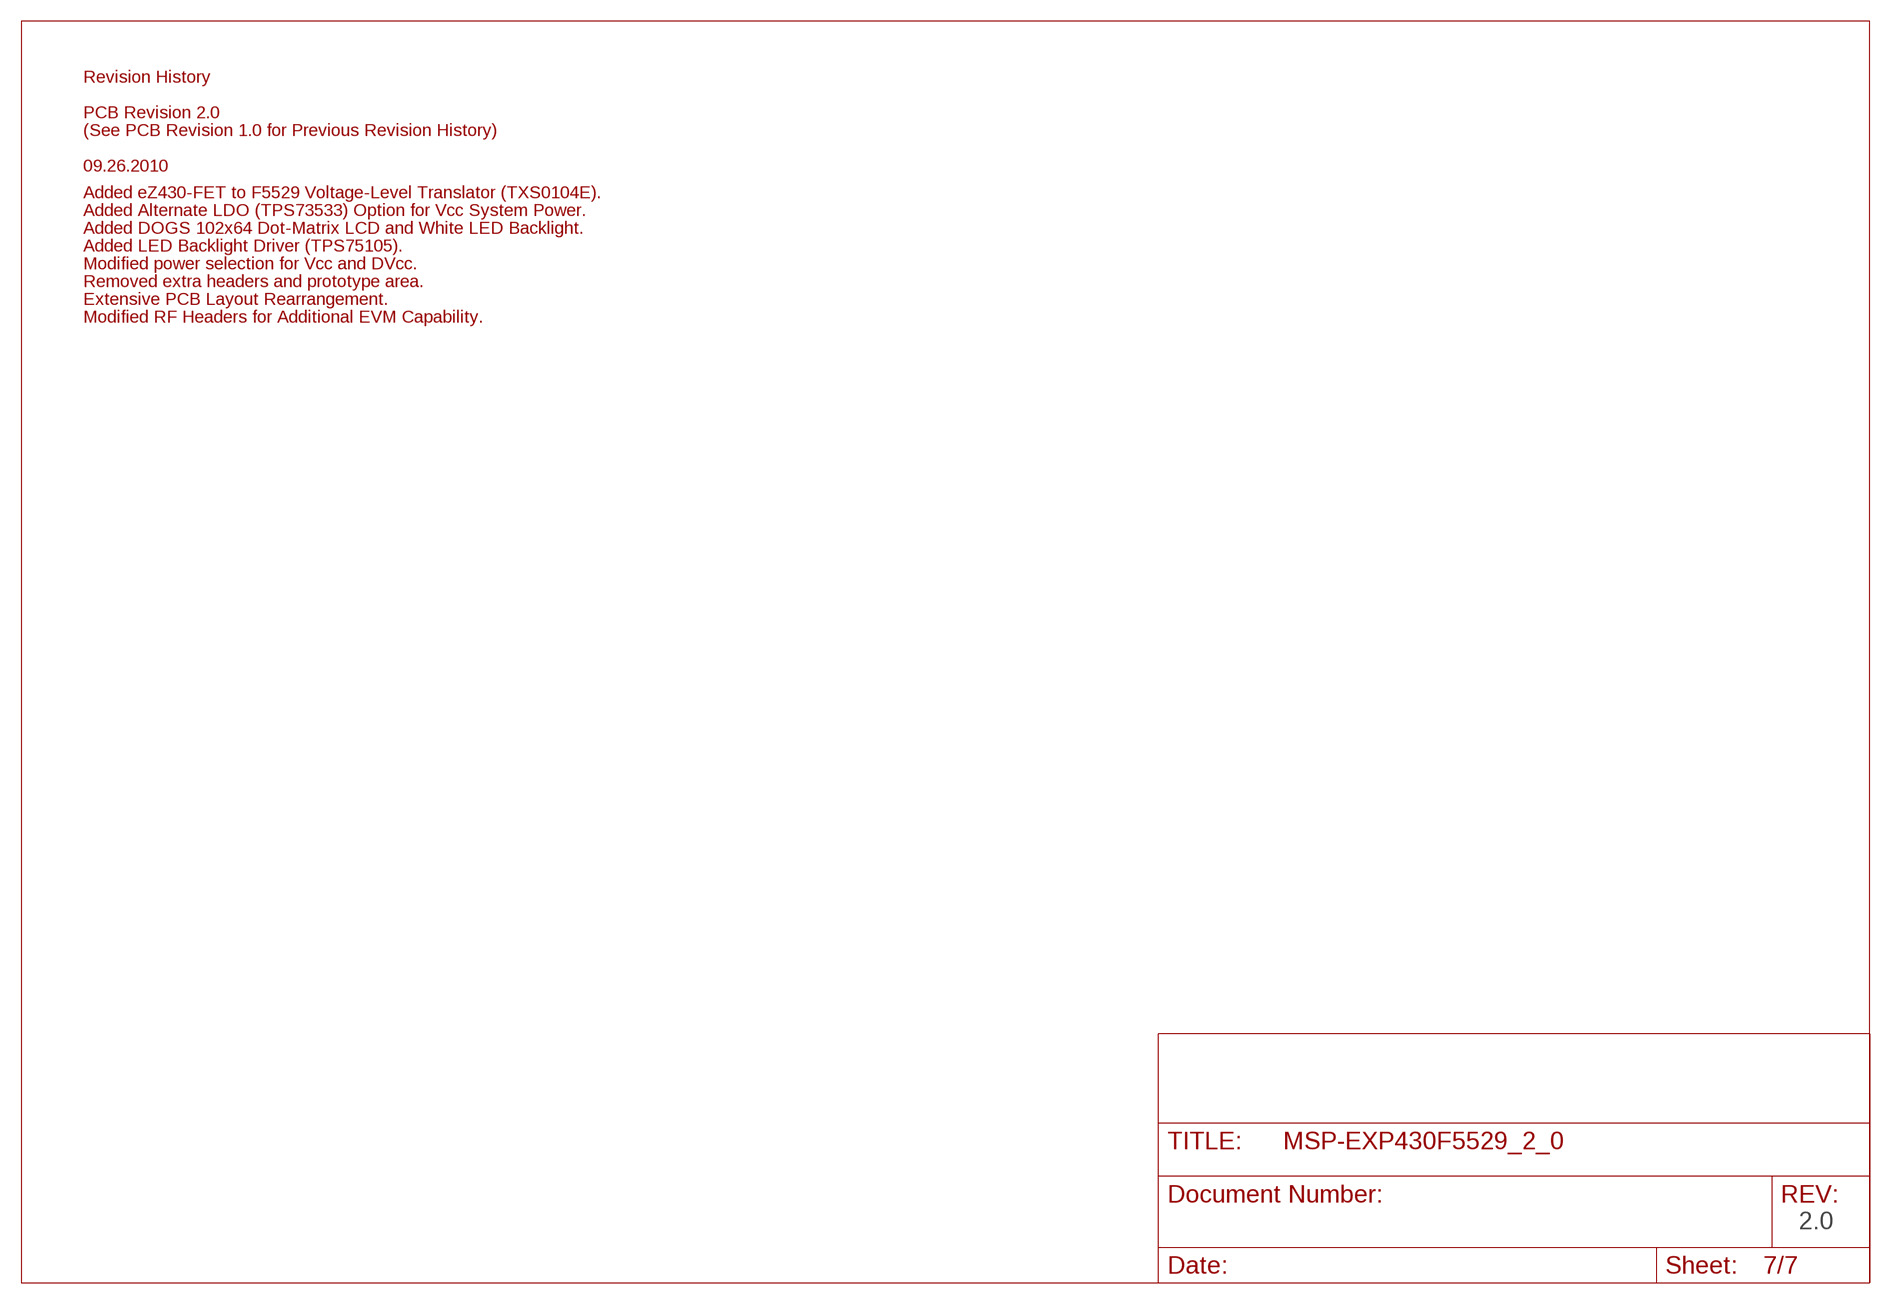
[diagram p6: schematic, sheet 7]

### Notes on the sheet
- Revision History
- PCB Revision 2.0
- (See PCB Revision 1.0 for Previous Revision History)
- 09.26.2010
- Added eZ430-FET to F5529 Voltage-Level Translator (TXS0104E).
- Added Alternate LDO (TPS73533) Option for Vcc System Power.
- Added DOGS 102x64 Dot-Matrix LCD and White LED Backlight.
- Added LED Backlight Driver (TPS75105).
- Modified power selection for Vcc and DVcc.
- Removed extra headers and prototype area.
- Extensive PCB Layout Rearrangement.
- Modified RF Headers for Additional EVM Capability.
- 2.0

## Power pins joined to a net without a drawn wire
GND: U4.2(GND) U4.6(GND) U4.7(GND) U4.PP@1(GND) U4.PP@2(GND) U4.PP@3(GND) U4.PP@4(GND) U4.PP@5(GND) U4.TH(GND) U4.TH@1(GND) U4.TH@2(GND) U5.P$1(GND) U5.P$2(GND) U5.P$3(GND) U5.P$4(GND) U5.P$5(GND) U5.PP(GND)

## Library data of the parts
C1 C2 C4-C7 C18 C19 C22-C30 C32 = CAP:CSMD0805
C3 C8 C9 C11-C14 C16 C17 C33-C36 = rcl:C-EU: CAPACITOR, European symbol
C10 C15 C50 = smd:ELKO_1210
C20 C21 C31 = rcl:C-US: CAPACITOR, American symbol
C37-C49 = smd:C_SMD
CON1-CON3 = _MSP430:8PIN_SM_MA_HEADER
D1 = diode:SCHOTTKY-MINI-MELF
D2 = diode:DIODE-: DIODE
J1 = CON-ML:ML14: HARTING
J4 J5 = pinhead:PINHD-2X7: PIN HEADER
J9 = Project7264:MOLEX3PIN: Molex 3Pin connector, RM 2,5mm, H=5,9mm, Digi Key Nr.: WM18887-ND; MOLEX-NR: 22-03-5035
J10 JP8 JP11 = pinhead:PINHD-1X3: PIN HEADER
J12 = MSP-EXP430F5529_2_0:_MSP430_RF_MA09-2: PIN HEADER
J13 = Project7264:SL127P6
J17 = susbfet:SL127L6TH
JP2 JP3 JP6 JP7 JP14 JP15 = jumper:JP1E: JUMPER
JP16 = sTI Lib:JP5Q: JUMPER
LED1-LED8 = led:LED: LED
LED9 = smd:LED_0603
PAD1-PAD5 = MSP-EXP430F5529_2_0:PROJECT7264_CC430_PAD: Touch Pad, 10,10mm
POT1 = MSP430_ZAX:EVL-HFAA05B54
Q1 = MSP-EXP430F5438:F20XX_PIR_DEMO_&_EVAL_CM200T
Q2 = Project7264:QUARZ_HC49_4P: Quarz HC49/4H Sonderform mit 4 Pins, Höhe 4mm
Q3 = susbfet:XTL_FT7A
R1 R2 R6 R12-R27 = rcl:R-US_: RESISTOR, American symbol
R3-R5 = _MSP430:R-US_: RESISTOR, American symbol
R7-R11 = _MSP430:RES
R28-R54 = smd:R_SMD
RF1 RF2 = _MSP430_RF:TFM-110-02-SM-D-A-K
S1-S4 = electricalmeter:PB: OMRON SWITCH
SW1 = _5438_ATC:3PDT
TP1-TP8 = _5438_ATC:TP
TP9-TP15 = usbfet:TP05
U1 = TI_MSP430_v16_intern:F552X---PN80: ***MSP430F552X***PN80 http://www.ti.com/lit/gpn/msp430f5529 Rev1.0 06/2010 For F552X where X is 1,5,7,9
U2 = Project7264:CMA3000-D01: CMA300-D01 3-Axis ultra lowpower accelerometer with digital SPI and I²C interface. VTI-Technologies
U3 = ea:EADOGS102-6: HIGH-CONTRAST102x64 PIXEL LCD SUPERTWIST DISPLAY WITH LED BACKLIGHT UC1701 CONTROLLER WITH SPI (4-WIRE) INTERFACE
U4 = texas:TPS735*: 500mA, Low Quiescent Current, Ultra-Low Noise, High PSRR Low Dropout Linear Regulator
U5 = texas:TPS7510X: Low Dropout, Two-Bank LED Driver with PWM Brightness Control
U6 U11 = Project7264:TPD2E001: TPD2E001 ESD-protection diode array
U7 = TI_MSP430_v11:F16X---PM64: *** MSP430F16x *** PM64
U8 = texas:TXS0104E: 4-BIT BIDIRECTIONAL VOLTAGE-LEVEL TRANSLATOR FOR OPEN-DRAIN AND PUSH-PULL APPLICATIONS
U9 = gangprog:TPS773XX: VReg, 250mA
U10 = usbfet:TUSB3410: TI: TUSB3410: USB2UART-Controller
U12 = MSP-EXP430F5529_2_0:USBFET_M24XXX: Serial EEProm: 24LC xxx
USB1 USB2 = _con-usb-2:USB: USB Connectors
X1 = Project7264:SD-502702-003: SD-Micro Card connector, Hersteller Molex, H=1,53mm

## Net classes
0 Default: width 0.254 mm, drill 0.305 mm, clearance 0.152 mm
1 Ground: width 0.305 mm, drill 0.305 mm, clearance 0.152 mm to class 0, clearance 0.152 mm
2 Power: width 0.406 mm, drill 0.305 mm, clearance 0.152 mm to class 0, clearance 0.152 mm to class 1, clearance 0.152 mm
